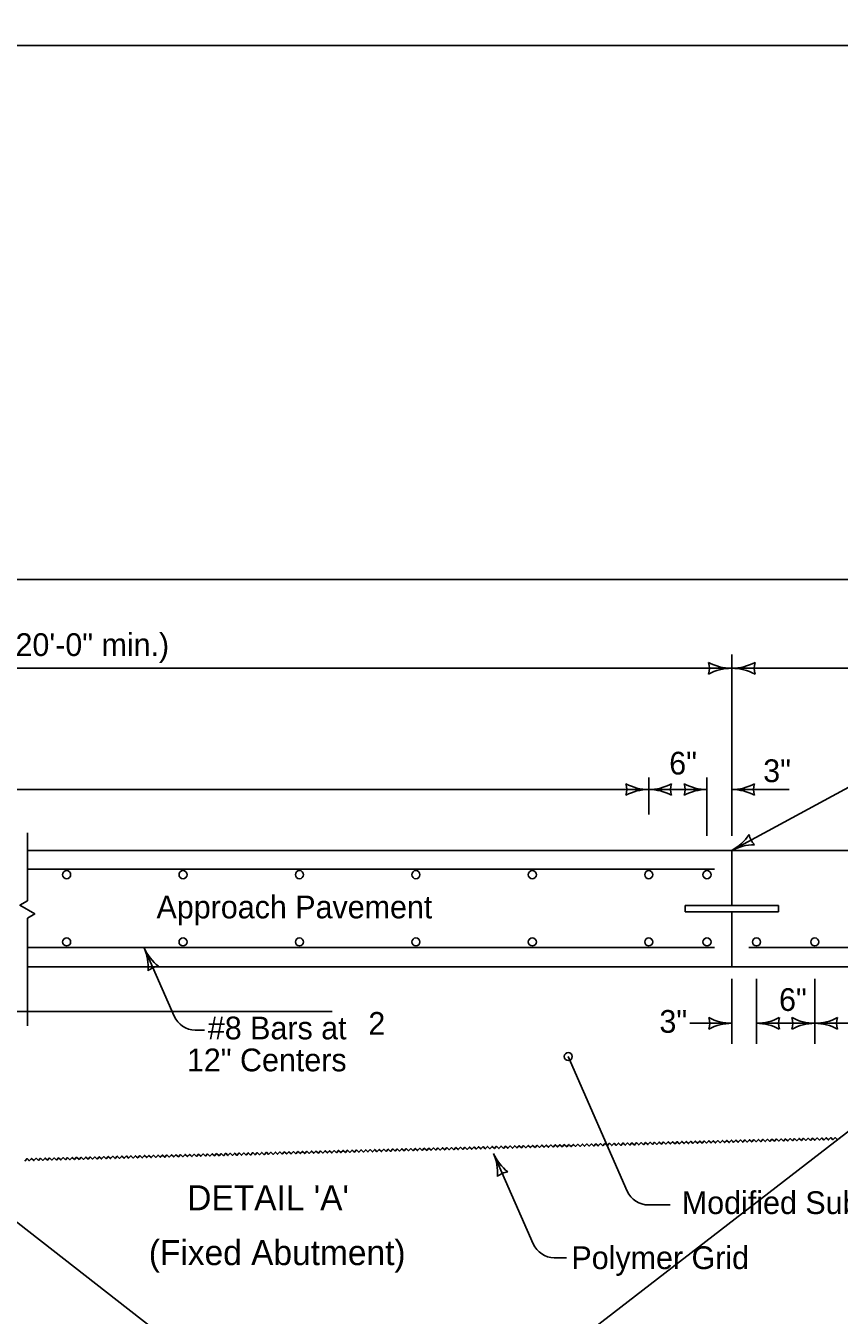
# Model space of a CAD drawing. Extents: x 8925 to 81668, y 4369 to 11918.
# Drawn here: x 11275 to 11989, y 6087 to 7221 of the extents above; entities that cross this region are included whole.
import ezdxf

# ---------------------------------------------------------------- set-up
doc = ezdxf.new("R2010")
doc.units = 0
for name, color, linetype in [('dsnShtPlotShapeBatchPrint', 7, 'Continuous'), ('dsnStdBlock', 7, 'Continuous'), ('dsnStdBlockNotModified', 7, 'Continuous'), ('dsnStdBorder', 7, 'Continuous'), ('Level 3', 7, 'Continuous'), ('Level 5', 7, 'Continuous'), ('SheetBorder', 7, 'Continuous')]:
    doc.layers.add(name, color=color, linetype=linetype)

msp = doc.modelspace()

# ---------------------------------------------------------------- linework, layer by layer
at = {"layer": 'dsnShtPlotShapeBatchPrint'}
for p, q in [((11894.8, 6508.6), (11894.8, 6667.8)), ((10523.2, 6655.8), (11894.8, 6655.8)), ((11894.8, 6655.8), (12863.5, 6655.8)), ((11894.8, 6495.6), (12058, 6583.9)), ((11821.9, 6527.3), (11821.9, 6559.8)), ((11873.1, 6508.6), (11873.1, 6559.8)), ((11821.9, 6549.2), (11209.4, 6549.2)), ((11873.1, 6549.2), (11821.9, 6549.2)), ((11945.2, 6549.2), (11894.8, 6549.2)), ((11894.8, 6447.3), (11894.8, 6495.6)), ((11894.8, 6495.6), (12371.2, 6495.6)), ((11894.8, 6495.6), (12371.2, 6495.6)), ((11935.8, 6447.3), (11894.8, 6447.3)), ((11894.8, 6393.3), (11894.8, 6441.6)), ((11894.8, 6441.6), (11935.8, 6441.6)), ((11935.8, 6441.6), (11935.8, 6447.3)), ((11378.5, 6410), (11404.9, 6349.8)), ((11894.8, 6393.3), (11275.9, 6393.3)), ((12371.2, 6393.3), (11894.8, 6393.3)), ((12371.2, 6393.3), (11894.8, 6393.3)), ((11894.8, 6325.7), (11894.8, 6382.8)), ((11916.6, 6325.7), (11916.6, 6382.8)), ((11967.8, 6325.7), (11967.8, 6382.8)), ((11250.3, 6353.9), (11543.7, 6353.9)), ((11894.8, 6343.6), (11858, 6343.6)), ((11967.8, 6343.6), (11916.6, 6343.6)), ((12790.5, 6343.6), (11967.8, 6343.6)), ((11423.4, 6337.7), (11431.5, 6337.7)), ((11751.2, 6314.4), (11803, 6196)), ((11685.5, 6229.2), (11720.4, 6149.6)), ((11821.6, 6183.9), (11840.7, 6183.9)), ((11738.9, 6137.5), (11749.7, 6137.5))]:
    msp.add_line(p, q, dxfattribs=at)
for points in [[(11705.1, 6234.9), (11706.1, 6234), (11708, 6236), (11710.1, 6234.1), (11712, 6236.1), (11714, 6234.2), (11716, 6236.2), (11718, 6234.3), (11719.9, 6236.3), (11722, 6234.4), (11723.9, 6236.4), (11726, 6234.5), (11727.9, 6236.5), (11729.9, 6234.6), (11731.9, 6236.6), (11733.9, 6234.7), (11735.8, 6236.7), (11737.9, 6234.8), (11739.8, 6236.8), (11741.8, 6234.9), (11743.8, 6236.9), (11745.8, 6235), (11747.7, 6237), (11749.8, 6235.1), (11751.7, 6237.1), (11752.7, 6236.2)], [(11752.7, 6236.2), (11753.7, 6235.2), (11755.7, 6237.2), (11757.7, 6235.3), (11759.6, 6237.3), (11761.7, 6235.4), (11763.6, 6237.4), (11765.6, 6235.5), (11767.6, 6237.5), (11769.6, 6235.6), (11771.5, 6237.6), (11773.6, 6235.7), (11775.5, 6237.7), (11777.5, 6235.8), (11779.5, 6237.9), (11781.5, 6235.9), (11783.4, 6238), (11785.5, 6236), (11787.4, 6238.1), (11789.4, 6236.1), (11791.4, 6238.2), (11793.4, 6236.2), (11795.3, 6238.3), (11797.4, 6236.3), (11799.3, 6238.4), (11800.3, 6237.4)], [(11800.3, 6237.4), (11801.3, 6236.4), (11803.3, 6238.5), (11805.3, 6236.5), (11807.2, 6238.6), (11809.3, 6236.6), (11811.2, 6238.7), (11813.2, 6236.7), (11815.2, 6238.8), (11817.2, 6236.9), (11819.1, 6238.9), (11821.2, 6237), (11823.1, 6239), (11825.1, 6237.1), (11827.1, 6239.1), (11829.1, 6237.2), (11831, 6239.2), (11833.1, 6237.3), (11835, 6239.3), (11837, 6237.4), (11839, 6239.4), (11841, 6237.5), (11842.9, 6239.5), (11845, 6237.6), (11846.9, 6239.6), (11847.9, 6238.6)], [(11847.9, 6238.6), (11848.9, 6237.7), (11850.9, 6239.7), (11852.9, 6237.8), (11854.8, 6239.8), (11856.9, 6237.9), (11858.8, 6239.9), (11860.8, 6238), (11862.8, 6240), (11864.8, 6238.1), (11866.7, 6240.1), (11868.8, 6238.2), (11870.7, 6240.2), (11872.7, 6238.3), (11874.7, 6240.3), (11876.7, 6238.4), (11878.6, 6240.4), (11880.7, 6238.5), (11882.6, 6240.5), (11884.6, 6238.6), (11886.6, 6240.6), (11888.6, 6238.7), (11890.5, 6240.7), (11892.6, 6238.8), (11894.5, 6240.9), (11895.5, 6239.9)], [(11895.5, 6239.9), (11896.5, 6238.9), (11898.5, 6241), (11900.5, 6239), (11902.4, 6241.1), (11904.5, 6239.1), (11906.4, 6241.2), (11908.4, 6239.2), (11910.4, 6241.3), (11912.4, 6239.3), (11914.3, 6241.4), (11916.4, 6239.4), (11918.3, 6241.5), (11920.4, 6239.5), (11922.3, 6241.6), (11924.3, 6239.6), (11926.3, 6241.7), (11928.3, 6239.8), (11930.2, 6241.8), (11932.3, 6239.9), (11934.2, 6241.9), (11936.2, 6240), (11938.2, 6242), (11940.2, 6240.1), (11942.1, 6242.1), (11943.1, 6241.1)], [(11943.1, 6241.1), (11944.2, 6240.2), (11946.1, 6242.2), (11948.1, 6240.3), (11950.1, 6242.3), (11952.1, 6240.4), (11954, 6242.4), (11956.1, 6240.5), (11958, 6242.5), (11960, 6240.6), (11962, 6242.6), (11964, 6240.7), (11965.9, 6242.7), (11968, 6240.8), (11969.9, 6242.8), (11971.9, 6240.9), (11973.9, 6242.9), (11975.9, 6241), (11977.8, 6243), (11979.9, 6241.1), (11981.8, 6243.1), (11983.8, 6241.2), (11985.8, 6243.2), (11987.8, 6241.3), (11989.7, 6243.3)], [(11276.6, 6223.7), (11277.6, 6222.8), (11279.6, 6224.8), (11281.6, 6222.9), (11283.5, 6224.9), (11285.6, 6223), (11287.5, 6225), (11289.5, 6223.1), (11291.5, 6225.1), (11293.5, 6223.2), (11295.4, 6225.2), (11297.5, 6223.3), (11299.4, 6225.3), (11301.4, 6223.4), (11303.4, 6225.4), (11305.4, 6223.5), (11307.3, 6225.5), (11309.4, 6223.6), (11311.3, 6225.6), (11313.3, 6223.7), (11315.3, 6225.7), (11317.3, 6223.8), (11319.2, 6225.8), (11321.3, 6223.9), (11323.2, 6225.9), (11324.2, 6225)], [(11324.2, 6225), (11325.2, 6224), (11327.2, 6226), (11329.2, 6224.1), (11331.1, 6226.1), (11333.2, 6224.2), (11335.1, 6226.2), (11337.2, 6224.3), (11339.1, 6226.3), (11341.1, 6224.4), (11343.1, 6226.5), (11345.1, 6224.5), (11347, 6226.6), (11349.1, 6224.6), (11351, 6226.7), (11353, 6224.7), (11354.9, 6226.8), (11357, 6224.8), (11358.9, 6226.9), (11361, 6224.9), (11362.9, 6227), (11364.9, 6225), (11366.9, 6227.1), (11368.9, 6225.1), (11370.8, 6227.2), (11371.8, 6226.2)], [(11371.8, 6226.2), (11372.9, 6225.2), (11374.8, 6227.3), (11376.8, 6225.3), (11378.8, 6227.4), (11380.8, 6225.5), (11382.7, 6227.5), (11384.8, 6225.6), (11386.7, 6227.6), (11388.7, 6225.7), (11390.7, 6227.7), (11392.7, 6225.8), (11394.6, 6227.8), (11396.7, 6225.9), (11398.6, 6227.9), (11400.6, 6226), (11402.6, 6228), (11404.6, 6226.1), (11406.5, 6228.1), (11408.6, 6226.2), (11410.5, 6228.2), (11412.5, 6226.3), (11414.5, 6228.3), (11416.5, 6226.4), (11418.4, 6228.4), (11419.4, 6227.5)], [(11419.4, 6227.5), (11420.5, 6226.5), (11422.4, 6228.5), (11424.4, 6226.6), (11426.4, 6228.6), (11428.4, 6226.7), (11430.3, 6228.7), (11432.4, 6226.8), (11434.3, 6228.8), (11436.3, 6226.9), (11438.3, 6228.9), (11440.3, 6227), (11442.2, 6229), (11444.3, 6227.1), (11446.2, 6229.1), (11448.2, 6227.2), (11450.2, 6229.3), (11452.2, 6227.3), (11454.1, 6229.4), (11456.2, 6227.4), (11458.1, 6229.5), (11460.1, 6227.5), (11462.1, 6229.6), (11464.1, 6227.6), (11466, 6229.7), (11467.1, 6228.7)], [(11467.1, 6228.7), (11468.1, 6227.7), (11470, 6229.8), (11472, 6227.8), (11474, 6229.9), (11476, 6227.9), (11477.9, 6230), (11480, 6228), (11481.9, 6230.1), (11483.9, 6228.1), (11485.9, 6230.2), (11487.9, 6228.3), (11489.8, 6230.3), (11491.9, 6228.4), (11493.8, 6230.4), (11495.8, 6228.5), (11497.8, 6230.5), (11499.8, 6228.6), (11501.7, 6230.6), (11503.8, 6228.7), (11505.7, 6230.7), (11507.7, 6228.8), (11509.7, 6230.8), (11511.7, 6228.9), (11513.6, 6230.9), (11514.7, 6229.9)], [(11514.7, 6229.9), (11515.7, 6229), (11517.6, 6231), (11519.6, 6229.1), (11521.6, 6231.1), (11523.6, 6229.2), (11525.5, 6231.2), (11527.6, 6229.3), (11529.5, 6231.3), (11531.6, 6229.4), (11533.5, 6231.4), (11535.5, 6229.5), (11537.5, 6231.5), (11539.5, 6229.6), (11541.4, 6231.6), (11543.5, 6229.7), (11545.4, 6231.7), (11547.4, 6229.8), (11549.3, 6231.8), (11551.4, 6229.9), (11553.3, 6231.9), (11555.4, 6230), (11557.3, 6232.1), (11559.3, 6230.1), (11561.3, 6232.1), (11562.3, 6231.2)], [(11562.3, 6231.2), (11563.3, 6230.2), (11565.2, 6232.3), (11567.3, 6230.3), (11569.2, 6232.4), (11571.2, 6230.4), (11573.2, 6232.5), (11575.2, 6230.5), (11577.1, 6232.6), (11579.2, 6230.6), (11581.1, 6232.7), (11583.1, 6230.7), (11585.1, 6232.8), (11587.1, 6230.8), (11589, 6232.9), (11591.1, 6230.9), (11593, 6233), (11595, 6231), (11597, 6233.1), (11599, 6231.2), (11600.9, 6233.2), (11603, 6231.3), (11604.9, 6233.3), (11606.9, 6231.4), (11608.9, 6233.4), (11609.9, 6232.4)], [(11609.9, 6232.4), (11610.9, 6231.5), (11612.8, 6233.5), (11614.9, 6231.6), (11616.8, 6233.6), (11618.8, 6231.7), (11620.8, 6233.7), (11622.8, 6231.8), (11624.7, 6233.8), (11626.8, 6231.9), (11628.7, 6233.9), (11630.7, 6232), (11632.7, 6234), (11634.7, 6232.1), (11636.6, 6234.1), (11638.7, 6232.2), (11640.6, 6234.2), (11642.6, 6232.3), (11644.6, 6234.3), (11646.6, 6232.4), (11648.5, 6234.4), (11650.6, 6232.5), (11652.5, 6234.5), (11654.5, 6232.6), (11656.5, 6234.6), (11657.5, 6233.7)], [(11657.5, 6233.7), (11658.5, 6232.7), (11660.4, 6234.7), (11662.5, 6232.8), (11664.4, 6234.8), (11666.4, 6232.9), (11668.4, 6234.9), (11670.4, 6233), (11672.3, 6235.1), (11674.4, 6233.1), (11676.3, 6235.2), (11678.3, 6233.2), (11680.3, 6235.3), (11682.3, 6233.3), (11684.2, 6235.4), (11686.3, 6233.4), (11688.2, 6235.5), (11690.2, 6233.5), (11692.2, 6235.6), (11694.2, 6233.6), (11696.1, 6235.7), (11698.2, 6233.7), (11700.1, 6235.8), (11702.1, 6233.8), (11704.1, 6235.9), (11705.1, 6234.9)], [(11276.9, 6223.6), (11275.7, 6224.7), (11273.6, 6222.4)]]:
    msp.add_lwpolyline(points, dxfattribs=at)
for centre in [(11423.4, 6357.9), (11821.6, 6204.1), (11738.9, 6157.7)]:
    msp.add_arc(centre, 20.2, 203.6401, 270, dxfattribs=at)
at = {"layer": 'dsnStdBlock'}
msp.add_lwpolyline([(10103, 6733.9), (13238, 6733.9), (13238, 4723.9), (10103, 4723.9)], close=True, dxfattribs=at)
at = {"layer": 'dsnStdBlockNotModified'}
msp.add_lwpolyline([(9998.5, 4619.4), (13342.5, 4619.4), (13342.5, 7203.4), (9998.5, 7203.4)], close=True, dxfattribs=at)
at = {"layer": 'dsnStdBorder'}
for p, q in [((11275.9, 6511.2), (11275.9, 6451.2)), ((11894.8, 6495.6), (11275.9, 6495.6)), ((11275.9, 6451.2), (11275.9, 6495.6)), ((11275.9, 6495.6), (11894.8, 6495.6)), ((11894.8, 6447.3), (11894.8, 6495.6)), ((11894.8, 6495.6), (11894.8, 6447.3)), ((11879.8, 6479.3), (11275.9, 6479.3)), ((11275.9, 6451.2), (11275.9, 6451.2)), ((11853.9, 6441.6), (11853.9, 6447.3)), ((11853.9, 6447.3), (11935.8, 6447.3)), ((11894.8, 6447.3), (11853.9, 6447.3)), ((11853.9, 6447.3), (11853.9, 6441.6)), ((11935.8, 6441.6), (11853.9, 6441.6)), ((11853.9, 6441.6), (11894.8, 6441.6)), ((11894.8, 6393.3), (11894.8, 6441.6)), ((11894.8, 6441.6), (11894.8, 6393.3)), ((11935.8, 6447.3), (11935.8, 6441.6)), ((11275.9, 6436), (11275.9, 6341.4)), ((11275.9, 6393.3), (11275.9, 6436)), ((11879.8, 6410.3), (11275.9, 6410.3)), ((11909.9, 6410.3), (12371.2, 6410.3)), ((11894.8, 6393.3), (11275.9, 6393.3))]:
    msp.add_line(p, q, dxfattribs=at)
msp.add_lwpolyline([(11275.9, 6436), (11282.4, 6439.8), (11269.3, 6447.4), (11275.9, 6451.2)], dxfattribs=at)
msp.add_lwpolyline([(11275.9, 6436), (11282.4, 6439.8), (11269.3, 6447.4), (11275.9, 6451.2)], dxfattribs=at)
for centre in [(11310.4, 6474.3), (11412.7, 6474.3), (11515, 6474.3), (11617.3, 6474.3), (11719.6, 6474.3), (11821.9, 6474.3), (11873.1, 6474.3), (11310.4, 6415.2), (11412.7, 6415.2), (11515, 6415.2), (11617.3, 6415.2), (11719.6, 6415.2), (11821.9, 6415.2), (11873.1, 6415.2), (11916.6, 6415.2), (11967.8, 6415.2)]:
    msp.add_circle(centre, 3.55, dxfattribs=at)
for centre, radius, start, end in [((11858.3, 6655.8), 16.9, 342.2666, 17.7333), ((11894.8, 6699.4), 43.6, 241.9275, 270), ((11894.8, 6612.2), 43.6, 90, 118.0725), ((11894.8, 6699.4), 43.6, 270, 298.0725), ((11894.8, 6612.2), 43.6, 61.9275, 90), ((11931.4, 6655.8), 16.9, 162.2666, 197.7334)]:
    msp.add_arc(centre, radius, start, end, dxfattribs=at)
at = {"layer": 'Level 3'}
for centre, radius, start, end in [((11786.3, 6549.2), 16.4, 342.2666, 17.7333), ((11821.9, 6591.7), 42.5, 241.9275, 270), ((11821.9, 6591.7), 42.5, 270, 298.0725), ((11857.5, 6549.2), 16.4, 162.2666, 197.7334), ((11837.4, 6549.2), 16.4, 342.2666, 17.7333), ((11873.1, 6591.7), 42.5, 241.9275, 270), ((11894.8, 6591.7), 42.5, 270, 298.0725), ((11930.5, 6549.2), 16.4, 162.2666, 197.7334), ((11821.9, 6506.7), 42.5, 90, 118.0725), ((11821.9, 6506.7), 42.5, 61.9275, 90), ((11873.1, 6506.7), 42.5, 90, 118.0725), ((11894.8, 6506.7), 42.5, 61.9275, 90), ((11874.6, 6533), 42.5, 298.4258, 326.4983), ((11926.2, 6512.6), 16.4, 190.6925, 226.1592), ((11915.1, 6458.2), 42.5, 90.3533, 118.4258), ((11417.5, 6427.1), 42.5, 203.6401, 231.7126), ((11339.6, 6393), 42.5, 355.5676, 23.6401), ((11392.8, 6377.4), 16.4, 95.9068, 131.3735), ((11859.2, 6343.6), 16.4, 342.2666, 17.7333), ((11894.8, 6386.1), 42.5, 241.9275, 270), ((11894.8, 6301.1), 42.5, 90, 118.0725), ((11916.6, 6386.1), 42.5, 270, 298.0725), ((11916.6, 6301.1), 42.5, 61.9275, 90), ((11952.3, 6343.6), 16.4, 162.2666, 197.7334), ((11932.1, 6343.6), 16.4, 342.2666, 17.7333), ((11967.8, 6386.1), 42.5, 241.9275, 270), ((11967.8, 6301.1), 42.5, 90, 118.0725), ((11967.8, 6386.1), 42.5, 270, 298.0725), ((11967.8, 6301.1), 42.5, 61.9275, 90), ((12003.4, 6343.6), 16.4, 162.2666, 197.7334), ((11724.5, 6246.3), 42.5, 203.6401, 231.7126), ((11646.6, 6212.2), 42.5, 355.5676, 23.6401), ((11699.8, 6196.6), 16.4, 95.9068, 131.3735)]:
    msp.add_arc(centre, radius, start, end, dxfattribs=at)
at = {"layer": 'Level 5'}
msp.add_circle((11751.2, 6314.4), 3.54, dxfattribs=at)
at = {"layer": 'SheetBorder'}
for p, q in [((13555.2, 7452), (9727.1, 4495)), ((9795, 7316.3), (13574.6, 4369))]:
    msp.add_line(p, q, dxfattribs=at)

# ---------------------------------------------------------------- texts
at = {"layer": 'dsnShtPlotShapeBatchPrint'}
for s, height, p in [('Double Reinforced Section (20\'-0" min.)', 20, (10931, 6666.6)), ('6"', 20, (11839.9, 6562.4)), ('3"', 20, (11922.5, 6555.7)), ('Approach Pavement', 20, (11389.4, 6435.9)), ('6"', 20, (11936.4, 6354.5)), ('#8 Bars at', 20, (11434.5, 6329.5)), ('2', 20, (11575.5, 6333.5)), ('3"', 20, (11831.3, 6335.3)), ('12" Centers', 20, (11416.1, 6301.4)), ('Modified Subbase', 20, (11851, 6175.9)), ('(Fixed Abutment)', 22, (11382.6, 6131)), ('Polymer Grid', 20, (11754, 6127.5))]:
    msp.add_text(s, height=height, dxfattribs=at).set_placement(p)
at = {"layer": 'dsnStdBorder'}
msp.add_text("DETAIL 'A' ", height=22, dxfattribs=at).set_placement((11416.4, 6179.2))

doc.saveas('drawing.dxf')
